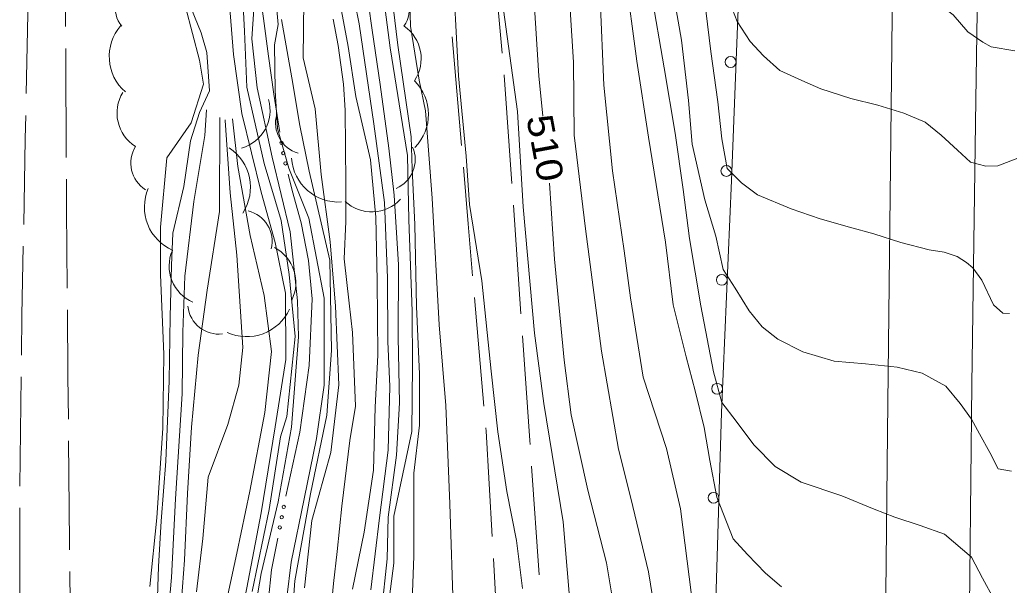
# Model space of a CAD drawing. Extents: x 2361284 to 2366480, y 6976556 to 6985346.
# Drawn here: x 2364293.2 to 2364474.8, y 6977677.6 to 6977781.3 of the extents above; entities that cross this region are included whole.
import ezdxf
from ezdxf.enums import TextEntityAlignment as Align

# ---------------------------------------------------------------- set-up
doc = ezdxf.new("R2010")
doc.units = 0
doc.header["$LTSCALE"] = 1.9
for name, color, linetype, lineweight in [('12', 7, 'Continuous', 13), ('13', 7, 'Continuous', 13), ('14', 7, 'Continuous', 13), ('15', 7, 'Continuous', 13), ('16', 7, 'Continuous', 13), ('17', 7, 'Continuous', 13), ('21', 7, 'Continuous', 13), ('3', 7, 'Continuous', 13)]:
    doc.layers.add(name, color=color, linetype=linetype, lineweight=lineweight)

msp = doc.modelspace()

# ---------------------------------------------------------------- linework, layer by layer
at = {"layer": '12'}
for points in [[(2364324.826, 6977926.024), (2364324.027, 6977915.395), (2364322.711, 6977904.463), (2364319.191, 6977890.648), (2364316.696, 6977878.544), (2364317.07, 6977872.877), (2364321.109, 6977858.224), (2364322.958, 6977851.152), (2364325.101, 6977845.562), (2364329.935, 6977834.617), (2364331.159, 6977830.075), (2364331.776, 6977820.824), (2364331.314, 6977808.458), (2364330.826, 6977797.733), (2364331.386, 6977787.239), (2364332.372, 6977774.957), (2364333.905, 6977764.151), (2364337.492, 6977749.714), (2364340.059, 6977740.507), (2364341.958, 6977731.206), (2364341.974, 6977719.014), (2364340.071, 6977706.697), (2364337.471, 6977690.88), (2364334.508, 6977675.551)], [(2364360.797, 6977673.621), (2364361.831, 6977681.672), (2364361.849, 6977690.272), (2364365.11, 6977705.825), (2364365.264, 6977718.006), (2364365.201, 6977727.887), (2364364.591, 6977744.662), (2364364.359, 6977756.45), (2364363.117, 6977764.008), (2364361.172, 6977776.201), (2364359.219, 6977791.264), (2364357.901, 6977807.851), (2364355.123, 6977825.505), (2364353.197, 6977840.869), (2364351.765, 6977851.605), (2364348.889, 6977860.559), (2364347.841, 6977882.47), (2364347.98, 6977898.363), (2364347.684, 6977901.11), (2364345.143, 6977907.516), (2364343.505, 6977912.42), (2364341.582, 6977924.273)], [(2364332.402, 6977923.276), (2364331.417, 6977914.355), (2364329.439, 6977902.577), (2364328.639, 6977888.887), (2364327.844, 6977877.85), (2364327.685, 6977869.327), (2364330.687, 6977860.725), (2364336.349, 6977850.999), (2364341.175, 6977838.804), (2364342.774, 6977828.378), (2364344.095, 6977814.711), (2364344.786, 6977807.206), (2364346.012, 6977792.908), (2364345.329, 6977784.83), (2364345.188, 6977774.388), (2364347.368, 6977765.02), (2364348.492, 6977752.949), (2364350.15, 6977740.613), (2364351.102, 6977728.823), (2364351.729, 6977714.387), (2364350.247, 6977701.983), (2364346.786, 6977689.489), (2364345.413, 6977677.156)], [(2364389.204, 6977763.646), (2364388.473, 6977771.06), (2364387.533, 6977785.632), (2364386.272, 6977803.71), (2364385.78, 6977824.907), (2364385.508, 6977841.916), (2364385.199, 6977859.694), (2364384.47, 6977876.399), (2364383.82, 6977893.232), (2364382.771, 6977900.533), (2364381.954, 6977912.805), (2364381.649, 6977922.794)], [(2364475.216, 6977698.521), (2364472.772, 6977698.988), (2364471.254, 6977701.964), (2364469.341, 6977705.386), (2364467.845, 6977708.092), (2364465.798, 6977710.922), (2364463.158, 6977714.136), (2364458.785, 6977716.525), (2364454.253, 6977717.592), (2364448.437, 6977718.197), (2364442.653, 6977718.732), (2364436.926, 6977720.448), (2364432.344, 6977722.735), (2364429.471, 6977725.038), (2364427.073, 6977727.975), (2364424.494, 6977732.091), (2364422.271, 6977735.55), (2364420.953, 6977741.656), (2364418.94, 6977748.318), (2364416.614, 6977758.497), (2364415.907, 6977766.561), (2364414.652, 6977777.619), (2364413.215, 6977785.706)], [(2364324.027, 6977784.938), (2364326.454, 6977778.941), (2364327.498, 6977775.36), (2364328.015, 6977768.335), (2364326.143, 6977764.317), (2364324.493, 6977759.121), (2364323.252, 6977750.749), (2364321.243, 6977742.168), (2364321.029, 6977736.287), (2364320.739, 6977726.824), (2364320.61, 6977715.121), (2364319.99, 6977700.366), (2364319.085, 6977689.355), (2364318.614, 6977681.042), (2364318.188, 6977668.016)], [(2364448.577, 6977573.081), (2364443.729, 6977575.054), (2364439.321, 6977576.893), (2364433.519, 6977579.267), (2364427.339, 6977581.189), (2364423.562, 6977582.993), (2364421.324, 6977584.822), (2364419.77, 6977590.648), (2364418.564, 6977599.617), (2364417.465, 6977604.856), (2364415.389, 6977614.898), (2364413.248, 6977626.538), (2364410.274, 6977639.52), (2364408.001, 6977647.189), (2364406.161, 6977653.472), (2364402.951, 6977669.242), (2364400.872, 6977681.714), (2364397.435, 6977695.041), (2364394.374, 6977708.863), (2364393.098, 6977718.87), (2364391.342, 6977737.436), (2364390.41, 6977751.347)]]:
    msp.add_lwpolyline(points, dxfattribs=at)
at = {"layer": '13'}
for points in [[(2364305.303, 6977932.478), (2364305.773, 6977920.852), (2364308.87, 6977906.511), (2364310.551, 6977894.836), (2364311.117, 6977883.71), (2364311.097, 6977877.351), (2364314.707, 6977864.774), (2364318.53, 6977854.93), (2364321.17, 6977844.444), (2364323.799, 6977828.918), (2364324.503, 6977817.965), (2364322.358, 6977802.733), (2364321.629, 6977792.996), (2364322.311, 6977788.693), (2364326.122, 6977773.947), (2364326.894, 6977769.544), (2364324.601, 6977762.462), (2364320.171, 6977756.01), (2364318.972, 6977743.328), (2364318.985, 6977734.528), (2364319.583, 6977720.022), (2364319.442, 6977706.451), (2364318.319, 6977689.978), (2364317.048, 6977677.407)], [(2364385.466, 6977677.037), (2364384.342, 6977685.826), (2364382.577, 6977694.789), (2364380.943, 6977705.765), (2364379.687, 6977716.893), (2364377.949, 6977733.438), (2364375.726, 6977747.478), (2364375.081, 6977756.342), (2364373.681, 6977771.089), (2364372.563, 6977793.001), (2364372.126, 6977802.116), (2364371.984, 6977816.036), (2364371.904, 6977834.926), (2364371.857, 6977842.996), (2364371.776, 6977851.526), (2364371.867, 6977856.707), (2364371.773, 6977869.797), (2364371.229, 6977881.722), (2364370.569, 6977892.226), (2364369.946, 6977903.122), (2364369.483, 6977910.807), (2364368.309, 6977920.677), (2364367.721, 6977930.902)], [(2364430.052, 6977679.811), (2364426.749, 6977683.22), (2364424.111, 6977686.154), (2364421.118, 6977693.776), (2364419.865, 6977700.485), (2364418.798, 6977706.525), (2364417.164, 6977713.299), (2364415.504, 6977719.524), (2364413.124, 6977729.052), (2364411.724, 6977740.52), (2364408.56, 6977759.84), (2364406.407, 6977773.74), (2364404.274, 6977789.832), (2364401.847, 6977813.77), (2364401.266, 6977825.404), (2364399.999, 6977837.673), (2364398.996, 6977857.985), (2364397.664, 6977876.034), (2364396.392, 6977895.242), (2364395.548, 6977906.155), (2364394.358, 6977932.485)], [(2364372.753, 6977672.005), (2364372.128, 6977692.53), (2364371.396, 6977710.585), (2364370.165, 6977725.394), (2364368.854, 6977748.632), (2364367.652, 6977764.663), (2364366.489, 6977770.251), (2364364.894, 6977780.156), (2364364.579, 6977791.185), (2364363.653, 6977810.697), (2364363.468, 6977826.005), (2364362.952, 6977849.772), (2364362.161, 6977862.357), (2364360.814, 6977868.572), (2364356.765, 6977876.855), (2364353.772, 6977884.446), (2364353.184, 6977889.646), (2364353.385, 6977896.796), (2364352.503, 6977900.126), (2364351.306, 6977901.924), (2364346.721, 6977910.82), (2364345.166, 6977916.686), (2364344.322, 6977928.619)], [(2364394.397, 6977671.731), (2364392.9, 6977689.217), (2364389.344, 6977710.965), (2364387.621, 6977723.86), (2364385.58, 6977747.021), (2364384.504, 6977764.542), (2364381.69, 6977784.946), (2364380.241, 6977801.633), (2364379.229, 6977822.855), (2364378.909, 6977837.603), (2364378.547, 6977856.78), (2364378.464, 6977868.64), (2364378.338, 6977880.789), (2364377.58, 6977901.594), (2364377.162, 6977915.12), (2364376.391, 6977926.814)], [(2364475.812, 6977775.64), (2364471.456, 6977776.369), (2364469.948, 6977777.225), (2364467.22, 6977779.109), (2364464.51, 6977782.253), (2364461.942, 6977784.139), (2364455.511, 6977787.349), (2364451.301, 6977790.439), (2364445.036, 6977794.17), (2364438.857, 6977796.161), (2364433.613, 6977798.65), (2364430.914, 6977800.505), (2364428.728, 6977803.224), (2364424.031, 6977810.281), (2364421.116, 6977817.113), (2364420.363, 6977822.666), (2364419.354, 6977833.097), (2364417.998, 6977850.555), (2364416.911, 6977869.236), (2364415.42, 6977883.002)], [(2364416.49, 6977675.811), (2364414.45, 6977691.622), (2364411.874, 6977702.669), (2364407.599, 6977715.778), (2364405.27, 6977730.338), (2364404.098, 6977738.987), (2364401.978, 6977753.657), (2364400.389, 6977769.333), (2364399.707, 6977785.337), (2364398.103, 6977803.653), (2364396.994, 6977814.054), (2364395.14, 6977832.307), (2364394.014, 6977858.187)], [(2364410.514, 6977668.024), (2364408.578, 6977680.077), (2364405.349, 6977693.586), (2364403.074, 6977702.576), (2364399.933, 6977720.537), (2364396.999, 6977742.99), (2364394.946, 6977760.191), (2364394.779, 6977773.56), (2364393.584, 6977792.93), (2364392.196, 6977813.758)], [(2364333.74, 6977792.061), (2364334.381, 6977779.256), (2364334.829, 6977768.96), (2364338.001, 6977754.999), (2364341.161, 6977744.529), (2364342.616, 6977734.592), (2364343.704, 6977723.252), (2364342.163, 6977708.547), (2364341.039, 6977704.816), (2364338.935, 6977691.534), (2364335.848, 6977676.475)], [(2364353.885, 6977788.463), (2364355.46, 6977780.616), (2364358.184, 6977762.271), (2364360.132, 6977747.809), (2364360.653, 6977734.034), (2364360.694, 6977722.304), (2364361.092, 6977714.096), (2364360.794, 6977702.364), (2364359.172, 6977689.967), (2364357.597, 6977676.762)], [(2364356.52, 6977789.018), (2364357.841, 6977779.419), (2364359.296, 6977769.452), (2364360.907, 6977757.767), (2364361.899, 6977749.146), (2364362.68, 6977736.383), (2364362.637, 6977723.092), (2364362.86, 6977711.094), (2364362.293, 6977701.448), (2364360.791, 6977690.092), (2364360.593, 6977682.471), (2364359.586, 6977672.67)], [(2364361.147, 6977788.322), (2364362.537, 6977776.674), (2364364.996, 6977759.896), (2364365.182, 6977754.018), (2364365.71, 6977743.762), (2364365.992, 6977728.764), (2364366.512, 6977716.308), (2364366.511, 6977706.948), (2364365.493, 6977698.168), (2364365.508, 6977682.958), (2364364.905, 6977666.36)], [(2364340.569, 6977780.465), (2364340.287, 6977783.872), (2364339.401, 6977785.534), (2364338.111, 6977785.522), (2364336.122, 6977783.313), (2364335.754, 6977777.879), (2364336.709, 6977768.878), (2364339.48, 6977756.163), (2364342.781, 6977742.454), (2364344.132, 6977729.796), (2364344.325, 6977723.168), (2364343.012, 6977706.635), (2364340.572, 6977692.93), (2364337.487, 6977679.771), (2364335.305, 6977667.359)], [(2364472.04, 6977674.999), (2364469.873, 6977678.91), (2364467.886, 6977682.751), (2364462.906, 6977686.953), (2364458.47, 6977688.581), (2364453.795, 6977690.096), (2364449.981, 6977691.56), (2364444.078, 6977694.034), (2364436.604, 6977696.503), (2364431.845, 6977699.419), (2364427.907, 6977703.382), (2364424.666, 6977707.731), (2364422.023, 6977711.156), (2364420.5, 6977716.741), (2364418.196, 6977728.861), (2364416.088, 6977741.19), (2364414.952, 6977750.231), (2364413.494, 6977760.517), (2364411.43, 6977772.538), (2364409.087, 6977786.387)], [(2364351.828, 6977784.962), (2364353.449, 6977776.457), (2364354.826, 6977767.281), (2364357.517, 6977755.645), (2364358.527, 6977745.114), (2364358.748, 6977733.526), (2364358.878, 6977719.815), (2364358.419, 6977710.281), (2364358.109, 6977698.718), (2364356.377, 6977687.33), (2364354.226, 6977676.9)], [(2364476.699, 6977756.058), (2364472.714, 6977754.56), (2364470.484, 6977754.499), (2364467.697, 6977755.202), (2364465.276, 6977757.449), (2364462.32, 6977760.161), (2364459.377, 6977762.534), (2364455.431, 6977764.206), (2364450.646, 6977765.692), (2364445.695, 6977766.925), (2364440.208, 6977768.683), (2364436.713, 6977770.208), (2364432.656, 6977772.02), (2364429.709, 6977774.702), (2364427.214, 6977777.388), (2364424.879, 6977781.026), (2364423.557, 6977784.354)], [(2364468.132, 6977735.826), (2364466.942, 6977736.824), (2364465.262, 6977737.888), (2364462.844, 6977738.735), (2364460.09, 6977739.159), (2364454.897, 6977740.5), (2364449.97, 6977742.082), (2364445.47, 6977743.291), (2364440.065, 6977744.839), (2364434.757, 6977746.669), (2364428.602, 6977749.22), (2364425.661, 6977751.413), (2364423.025, 6977754.068), (2364422.033, 6977759.518), (2364421.299, 6977766.303), (2364419.991, 6977775.55), (2364419.12, 6977783.022)], [(2364340.569, 6977780.465), (2364339.945, 6977776.739), (2364340.024, 6977768.389), (2364340.471, 6977761.393), (2364342.53, 6977754.112), (2364346.238, 6977744.957), (2364349.028, 6977730.283), (2364349.05, 6977714.331), (2364347.613, 6977704.538), (2364345.358, 6977693.445), (2364342.967, 6977681.833), (2364341.39, 6977668.907)], [(2364341.181, 6977781.411), (2364343.092, 6977770.718), (2364344.547, 6977761.922), (2364346.256, 6977753.588), (2364350.072, 6977737.273), (2364350.379, 6977720.675), (2364349.512, 6977708.807), (2364346.529, 6977694.357), (2364343.65, 6977678.449), (2364342.511, 6977662.467)], [(2364350.681, 6977781.471), (2364351.597, 6977776.649), (2364352.575, 6977769.518), (2364352.87, 6977764.752), (2364352.998, 6977751.292), (2364353.034, 6977744.362), (2364352.719, 6977737.508), (2364353.597, 6977729.376), (2364354.208, 6977723.952), (2364354.797, 6977710.457), (2364353.776, 6977704.177), (2364352.261, 6977692.121), (2364351.44, 6977683.794), (2364350.736, 6977677.947), (2364350.039, 6977670.249)], [(2364327.438, 6977764.85), (2364327.123, 6977760.116), (2364325.089, 6977747.986), (2364323.479, 6977734.29), (2364323.066, 6977724.026), (2364322.964, 6977712.713), (2364321.766, 6977693.451), (2364321.003, 6977679.044), (2364319.688, 6977663.82)], [(2364329.892, 6977763.423), (2364329.836, 6977746.151), (2364327.543, 6977731.759), (2364325.926, 6977719.842), (2364324.692, 6977706.601), (2364323.948, 6977694.422), (2364323.374, 6977682.237), (2364322.45, 6977670.007)], [(2364330.846, 6977762.972), (2364330.857, 6977762.872), (2364331.784, 6977749.58), (2364332.982, 6977738.181), (2364334.084, 6977721.21), (2364333.389, 6977714.313), (2364331.338, 6977707.084), (2364327.75, 6977697.408), (2364326.747, 6977686.158), (2364325.589, 6977676.408)], [(2364332.195, 6977763.164), (2364333.168, 6977754.433), (2364335.447, 6977741.753), (2364337.992, 6977730.788), (2364339.35, 6977720.461), (2364338.136, 6977709.308), (2364335.393, 6977694.841), (2364333.032, 6977683.509), (2364330.206, 6977670.47)], [(2364474.861, 6977727.439), (2364473.611, 6977727.497), (2364471.886, 6977729.081), (2364469.753, 6977733.551), (2364468.132, 6977735.826)], [(2364432.967, 6977677.299), (2364430.052, 6977679.811)]]:
    msp.add_lwpolyline(points, dxfattribs=at)
at = {"layer": '14'}
msp.add_lwpolyline([(2364461.091, 6978393.234), (2364460.286, 6978354.391), (2364459.916, 6978334.969), (2364459.698, 6978322.02), (2364459.601, 6978315.546), (2364459.472, 6978305.834), (2364459.016, 6978266.021), (2364458.426, 6978212.938), (2364458.107, 6978186.396), (2364457.625, 6978149.176), (2364456.975, 6978099.55), (2364456.669, 6978074.736), (2364456.508, 6978060.846), (2364456.202, 6978033.066), (2364455.611, 6977977.505), (2364455.297, 6977949.725), (2364454.805, 6977909.571), (2364454.132, 6977856.033), (2364453.812, 6977829.264), (2364453.221, 6977776.246), (2364452.462, 6977705.555), (2364452.074, 6977670.209)], dxfattribs=at)
at = {"layer": '15'}
for p, q in [((2364301.582, 6977780.104), (2364301.492, 6977800.104)), ((2364379.923, 6977795.161), (2364381.732, 6977775.246)), ((2364294.728, 6977787.8), (2364294.338, 6977767.805)), ((2364374.253, 6977758.304), (2364372.563, 6977778.229)), ((2364383.768, 6977747.324), (2364385.157, 6977727.376)), ((2364378.348, 6977710.481), (2364376.628, 6977730.405)), ((2364293.422, 6977715.813), (2364293.192, 6977695.81)), ((2364387.103, 6977699.454), (2364388.474, 6977679.506)), ((2364293.16, 6977691.809), (2364293.17, 6977671.808)), ((2364381.243, 6977662.555), (2364380.093, 6977682.526))]:
    msp.add_line(p, q, dxfattribs=at)
for points in [[(2364301.7, 6977756.104), (2364301.604, 6977774.604), (2364301.6, 6977776.104)], [(2364382.09, 6977771.259), (2364382.101, 6977771.169), (2364383.49, 6977751.312)], [(2364294.256, 6977763.804), (2364294.177, 6977759.483), (2364293.876, 6977743.809)], [(2364376.29, 6977734.392), (2364375.47, 6977743.895), (2364374.591, 6977754.317)], [(2364301.869, 6977732.105), (2364301.751, 6977746.534), (2364301.718, 6977752.104)], [(2364293.794, 6977739.807), (2364293.554, 6977727.175), (2364293.464, 6977719.813)], [(2364302.077, 6977708.106), (2364302.002, 6977715.984), (2364301.907, 6977728.105)], [(2364385.435, 6977723.389), (2364386.778, 6977704.161), (2364386.825, 6977703.441)], [(2364379.865, 6977686.523), (2364378.751, 6977705.884), (2364378.696, 6977706.494)], [(2364302.295, 6977684.106), (2364302.282, 6977685.435), (2364302.115, 6977704.106)], [(2364302.623, 6977660.108), (2364302.55, 6977662.567), (2364302.343, 6977680.107)]]:
    msp.add_lwpolyline(points, dxfattribs=at)
at = {"layer": '16'}
for centre, radius, start, end in [((2364316.365, 6977783.797), 5.755, 128.65813, 218.65813), ((2364358.935, 6977783.431), 5.755, 325.73149, 55.73149), ((2364318.217, 6977774.602), 8.637, 138.87294, 228.87294), ((2364359.645, 6977774.214), 7.201, 325.73149, 55.73149), ((2364359.545, 6977763.988), 8.637, 315.46336, 45.46336), ((2364318.204, 6977764.23), 7.201, 148.11107, 238.11107), ((2364331.895, 6977764.731), 7.201, 285.95708, 15.95708), ((2364345.863, 6977762.404), 5.755, 163.81179, 253.81179), ((2364319.296, 6977755.051), 5.755, 148.11107, 238.11107), ((2364326.868, 6977750.62), 8.637, 326.70313, 56.70313), ((2364359.989, 6977755.709), 5.755, 293.15, 23.15), ((2364351.658, 6977756.541), 8.637, 183.89263, 273.89263), ((2364324.674, 6977746.978), 8.637, 156.67324, 246.67324), ((2364357.776, 6977753.313), 7.201, 227.20976, 317.20976), ((2364333.729, 6977740.685), 5.755, 346.32528, 76.32528), ((2364327.778, 6977736.161), 7.201, 156.67324, 246.67324), ((2364336.648, 6977733.128), 7.201, 333.20154, 63.20154), ((2364329.735, 6977729.421), 5.755, 186.4153, 276.4153), ((2364334.806, 6977731.846), 8.637, 245.52773, 335.52773)]:
    msp.add_arc(centre, radius, start, end, dxfattribs=at)
at = {"layer": '17'}
msp.add_lwpolyline([(2364417.947, 6977503.656), (2364418.033, 6977518.786), (2364418.169, 6977533.909), (2364418.883, 6977585.019), (2364419.906, 6977636.132), (2364420.859, 6977672.722), (2364422.001, 6977709.306), (2364423.806, 6977751.845), (2364425.442, 6977794.393), (2364426.573, 6977848.967), (2364427.354, 6977903.548), (2364427.842, 6977944.754), (2364428.321, 6977985.96), (2364429.078, 6978056.702), (2364429.736, 6978127.442), (2364429.592, 6978174.103), (2364428.708, 6978220.757), (2364427.748, 6978255.45), (2364426.389, 6978290.129), (2364424.777, 6978320.776), (2364423.206, 6978351.412), (2364422.097, 6978377.613), (2364421.077, 6978403.814)], dxfattribs=at)
for centre in [(2364423.64, 6977773.596), (2364422.869, 6977753.611), (2364422.03, 6977733.632), (2364421.184, 6977713.65), (2364420.512, 6977693.65)]:
    msp.add_circle(centre, 1, dxfattribs=at)
at = {"layer": '21'}
for points in [[(2364336.369, 6977820.458), (2364336.436, 6977814.428), (2364336.499, 6977811.028), (2364336.571, 6977807.638), (2364336.69, 6977799.359), (2364336.838, 6977791.081), (2364337.234, 6977786.323), (2364337.879, 6977781.589), (2364338.815, 6977774.658), (2364339.791, 6977767.728), (2364340.687, 6977761.845), (2364340.877, 6977760.737)], [(2364342.42, 6977753.051), (2364343.179, 6977750.048), (2364344.826, 6977744.114), (2364346.173, 6977737.156), (2364346.809, 6977730.172), (2364346.265, 6977717.945), (2364344.571, 6977705.719), (2364342.022, 6977693.924)], [(2364340.505, 6977686.229), (2364339.361, 6977680.409), (2364338.263, 6977669.657), (2364337.555, 6977658.88), (2364337.22, 6977651.006), (2364337.185, 6977643.145), (2364337.781, 6977636.191), (2364338.437, 6977629.236), (2364338.453, 6977626.487)]]:
    msp.add_lwpolyline(points, dxfattribs=at)
for centre in [(2364341.204, 6977758.767), (2364341.523, 6977756.874), (2364341.923, 6977754.998), (2364341.627, 6977691.977), (2364341.258, 6977690.092), (2364340.889, 6977688.208)]:
    msp.add_circle(centre, 0.3, dxfattribs=at)
at = {"layer": '3'}
msp.add_lwpolyline([(2364476.86, 6978388.164), (2364475.657, 6978327.472), (2364475.184, 6978297.124), (2364474.229, 6978216.704), (2364473.831, 6978176.494), (2364473.557, 6978129.148), (2364473.275, 6978066.02), (2364472.942, 6978034.458), (2364470.275, 6977871.183), (2364468.653, 6977766.677), (2364467.925, 6977714.422), (2364467.22, 6977644.472), (2364466.924, 6977597.838), (2364466.55, 6977504.568)], dxfattribs=at)

# ---------------------------------------------------------------- texts
at = {"layer": '12', "width": 1.15}
msp.add_text(' 510 ', height=4.8, rotation=280.545, dxfattribs=at).set_placement((2364387.259, 6977757.391), align=Align.CENTER)

doc.saveas('drawing.dxf')
